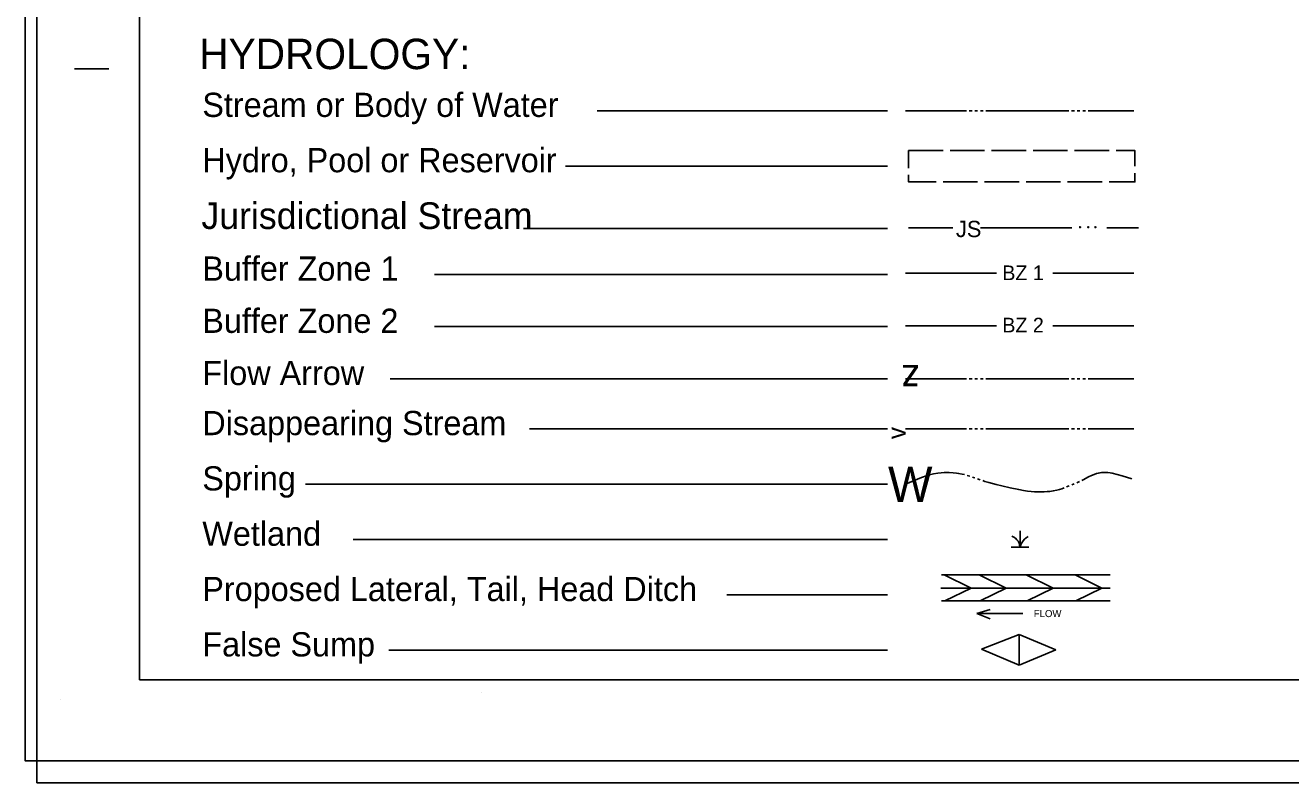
# Model space of a CAD drawing. Extents: x 811137 to 813186, y 647386 to 648494.
# Drawn here: x 811136.6 to 811598.2, y 647386.1 to 647662.4 of the extents above; entities that cross this region are included whole.
import ezdxf

# ---------------------------------------------------------------- set-up
doc = ezdxf.new("R2010")
doc.units = 0
for name, color, linetype in [('Default', 7, 'Continuous'), ('Sheet_Plan', 7, 'Continuous'), ('Sheet_Symbology', 7, 'Continuous'), ('z - Construction', 7, 'Continuous')]:
    doc.layers.add(name, color=color, linetype=linetype)

msp = doc.modelspace()

# ---------------------------------------------------------------- linework, layer by layer
at = {"layer": 'Default'}
for p, q in [((811154.58, 647646.52), (811167.08, 647646.52)), ((811149.63, 647416.47), (811149.63, 647416.47)), ((811303.08, 647419.02), (811303.08, 647419.02)), ((811303.08, 647419.02), (811303.08, 647419.02)), ((811136.63, 647394.02), (811136.63, 647394.02))]:
    msp.add_line(p, q, dxfattribs=at)
msp.add_lwpolyline([(812820.63, 648494.02), (811136.63, 648494.02), (811136.63, 647394.02), (812820.63, 647394.02)], close=True, dxfattribs=at)
at = {"layer": 'Sheet_Plan'}
for q in [(811178.27, 648448.58), (812803.25, 647423.58)]:
    msp.add_line((811178.28, 647423.58), q, dxfattribs=at)
at = {"layer": 'Sheet_Symbology'}
for p, q in [((811451.14, 647631.25), (811345.2, 647631.25)), ((811457.71, 647631.25), (811479.93, 647631.25)), ((811480.94, 647631.25), (811481.95, 647631.25)), ((811482.96, 647631.25), (811483.97, 647631.25)), ((811484.98, 647631.25), (811485.98, 647631.25)), ((811486.99, 647631.25), (811517.26, 647631.25)), ((811518.27, 647631.25), (811519.28, 647631.25)), ((811520.29, 647631.25), (811521.3, 647631.25)), ((811522.31, 647631.25), (811523.32, 647631.25)), ((811524.32, 647631.25), (811540.95, 647631.25)), ((811458.78, 647616.7), (811471.39, 647616.7)), ((811458.78, 647610.34), (811458.78, 647616.7)), ((811473.92, 647616.7), (811486.53, 647616.7)), ((811489.05, 647616.7), (811501.66, 647616.7)), ((811504.18, 647616.7), (811516.8, 647616.7)), ((811519.32, 647616.7), (811531.93, 647616.7)), ((811451.14, 647611.07), (811333.71, 647611.07)), ((811483.98, 647605.27), (811471.37, 647605.27)), ((811499.11, 647605.27), (811486.5, 647605.27)), ((811514.25, 647605.27), (811501.64, 647605.27)), ((811529.38, 647605.27), (811516.77, 647605.27)), ((811451.14, 647588.27), (811318.36, 647588.27)), ((811451.14, 647571.51), (811285.92, 647571.51)), ((811457.71, 647571.95), (811490.8, 647571.95)), ((811540.95, 647571.95), (811511.38, 647571.95)), ((811451.14, 647552.47), (811285.92, 647552.47)), ((811457.71, 647552.8), (811490.8, 647552.8)), ((811540.95, 647552.8), (811511.38, 647552.8)), ((811451.14, 647533.43), (811269.69, 647533.43)), ((811457.71, 647533.43), (811479.93, 647533.43)), ((811480.94, 647533.43), (811481.95, 647533.43)), ((811482.96, 647533.43), (811483.97, 647533.43)), ((811484.98, 647533.43), (811485.98, 647533.43)), ((811486.99, 647533.43), (811517.26, 647533.43)), ((811518.27, 647533.43), (811519.28, 647533.43)), ((811520.29, 647533.43), (811521.3, 647533.43)), ((811522.31, 647533.43), (811523.32, 647533.43)), ((811524.32, 647533.43), (811540.95, 647533.43)), ((811451.14, 647515.15), (811320.47, 647515.15)), ((811457.71, 647515.15), (811479.93, 647515.15)), ((811480.94, 647515.15), (811481.95, 647515.15)), ((811482.96, 647515.15), (811483.97, 647515.15)), ((811484.98, 647515.15), (811485.98, 647515.15)), ((811486.99, 647515.15), (811517.26, 647515.15)), ((811518.27, 647515.15), (811519.28, 647515.15)), ((811520.29, 647515.15), (811521.3, 647515.15)), ((811522.31, 647515.15), (811523.32, 647515.15)), ((811524.32, 647515.15), (811540.95, 647515.15)), ((811451.14, 647494.97), (811238.78, 647494.97)), ((811483.95, 647496.94), (811484.91, 647496.61)), ((811516.44, 647493.99), (811517.38, 647494.37)), ((811518.32, 647494.73), (811519.24, 647495.13)), ((811499.44, 647472.06), (811499.44, 647477.99)), ((811451.14, 647474.8), (811256.2, 647474.8)), ((811496.25, 647472.06), (811502.68, 647472.06)), ((811470.8, 647461.93), (811532.36, 647461.93)), ((811471.71, 647461.93), (811481.58, 647457.09)), ((811484.53, 647461.93), (811494.41, 647457.09)), ((811501.64, 647461.93), (811511.55, 647457.09)), ((811519.53, 647461.93), (811529.22, 647457.09)), ((811451.14, 647454.62), (811392.44, 647454.62)), ((811470.54, 647457.09), (811532.36, 647457.09)), ((811481.58, 647457.09), (811471.99, 647452.4)), ((811494.41, 647457.09), (811484.85, 647452.4)), ((811511.55, 647457.09), (811501.99, 647452.4)), ((811529.22, 647457.09), (811519.8, 647452.4)), ((811470.8, 647452.4), (811532.36, 647452.4)), ((811483.66, 647447.86), (811488.51, 647449.22)), ((811483.66, 647447.86), (811500.46, 647447.86)), ((811483.66, 647447.86), (811488.51, 647445.89)), ((811499.11, 647440.1), (811485.42, 647434.78)), ((811499.11, 647428.95), (811499.11, 647440.1)), ((811512.55, 647434.53), (811499.11, 647440.1)), ((811451.14, 647434.44), (811269.25, 647434.44)), ((811485.42, 647434.78), (811499.11, 647428.95)), ((811499.11, 647428.95), (811512.55, 647434.53))]:
    msp.add_line(p, q, dxfattribs=at)
for points in [[(811534.45, 647616.7), (811541.34, 647616.7), (811541.34, 647610.97)], [(811468.85, 647605.27), (811458.78, 647605.27), (811458.78, 647607.82)], [(811541.34, 647608.45), (811541.34, 647605.27), (811531.9, 647605.27)], [(811458.78, 647588.47), (811474.93, 647588.47)], [(811485.06, 647588.47), (811499.21, 647588.47)], [(811499.21, 647588.47), (811518.37, 647588.47)], [(811531.08, 647588.47), (811542.6, 647588.47)], [(811457.72, 647494.97), (811460.58, 647496.17), (811463.46, 647497.38), (811464.18, 647497.66), (811465.45, 647498.1), (811466.44, 647498.37), (811467.91, 647498.71), (811469.4, 647498.97), (811470.65, 647499.12), (811471.76, 647499.21), (811472.73, 647499.24), (811473.59, 647499.24), (811475.09, 647499.15), (811476.21, 647499.03), (811477.04, 647498.91), (811478.29, 647498.67), (811479.15, 647498.47)], [(811522, 647496.39), (811522.48, 647496.63), (811524.46, 647497.66), (811525.47, 647498.15), (811526.52, 647498.58), (811527.31, 647498.85), (811528.02, 647499.02), (811528.65, 647499.15), (811529.21, 647499.24), (811530.19, 647499.3), (811530.92, 647499.3), (811531.46, 647499.26), (811532.27, 647499.15), (811533.06, 647498.97), (811536.65, 647497.99), (811540.22, 647496.99)], [(811480.13, 647498.2), (811480.6, 647498.06), (811481.09, 647497.91)], [(811482.05, 647497.6), (811482.47, 647497.46), (811483.01, 647497.27)], [(811485.87, 647496.29), (811486.64, 647496.02), (811488.05, 647495.6), (811490.76, 647494.89), (811492.81, 647494.37), (811495.87, 647493.66), (811498.96, 647493.02), (811500.68, 647492.72), (811502.19, 647492.49), (811503.53, 647492.34), (811504.7, 647492.24), (811505.72, 647492.19), (811506.63, 647492.16), (811508.19, 647492.19), (811509.37, 647492.26), (811510.25, 647492.36), (811511.55, 647492.55), (811512.84, 647492.83), (811513.81, 647493.09), (811514.65, 647493.35), (811515.5, 647493.65)], [(811520.18, 647495.52), (811520.38, 647495.6), (811521.1, 647495.93)], [(811499.44, 647472.06), (811499.29, 647472.77), (811499.09, 647473.48), (811498.73, 647474.14), (811498.28, 647474.74), (811497.77, 647475.3), (811497.16, 647475.71), (811496.5, 647476.06)], [(811499.44, 647472.06), (811499.75, 647472.82), (811500.1, 647473.58), (811500.56, 647474.29), (811501.11, 647474.9), (811501.72, 647475.45), (811502.38, 647475.96)]]:
    msp.add_lwpolyline(points, dxfattribs=at)
for centre in [(811521.34, 647588.76), (811524.32, 647588.76), (811526.93, 647588.76)]:
    msp.add_ellipse(centre, major_axis=(0, 0.199), ratio=0.938496, dxfattribs=at)
at = {"layer": 'z - Construction'}
for p, q in [((811140.78, 648486.08), (811140.78, 647386.08)), ((811140.78, 647386.08), (812840.77, 647386.08))]:
    msp.add_line(p, q, dxfattribs=at)

# ---------------------------------------------------------------- texts
at = {"layer": 'Sheet_Symbology'}
for s, height, p in [('HYDROLOGY:', 11.098, (811200.04, 647646.41)), ('Stream or Body of Water', 8.8282, (811201.19, 647628.97)), ('Hydro, Pool or Reservoir', 8.8282, (811201.19, 647608.79)), ('Jurisdictional Stream', 9.7323, (811200.85, 647588.08)), ('JS', 5.958, (811476.05, 647585.12)), ('Buffer Zone 1', 8.8282, (811201.19, 647569.23)), ('BZ 1', 5.362, (811492.97, 647569.42)), ('Buffer Zone 2', 8.8282, (811201.19, 647550.19)), ('BZ 2', 5.362, (811492.97, 647550.35)), ('Flow Arrow', 8.828, (811201.19, 647531.15)), ('Disappearing Stream', 8.8282, (811201.19, 647512.87)), ('Spring', 8.828, (811201.19, 647492.69)), ('W', 12.86, (811451.29, 647488.54)), ('Wetland', 8.828, (811201.19, 647472.51)), ('Proposed Lateral, Tail, Head Ditch', 8.8282, (811201.19, 647452.33)), ('FLOW', 2.616, (811504.44, 647446.49)), ('False Sump', 8.828, (811201.19, 647432.15))]:
    msp.add_text(s, height=height, dxfattribs=at).set_placement(p)
for s, height, rotation, p in [('z', 10.09, 180, (811462.77, 647538.48)), ('v', 6.66, 89.7591, (811457.71, 647511.38))]:
    msp.add_text(s, height=height, rotation=rotation, dxfattribs=at).set_placement(p)

doc.saveas('drawing.dxf')
